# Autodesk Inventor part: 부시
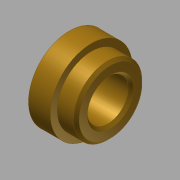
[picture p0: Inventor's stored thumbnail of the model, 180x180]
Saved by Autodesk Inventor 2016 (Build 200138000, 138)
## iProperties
Created: 2016-05
Part Number: 부시
Document SubType Name: Modeling
Designer: mduedu
Density: 7.86 g/cm^3
Material: 강철, 연강
Appearance: 황동 - 새틴
Author: mduedu
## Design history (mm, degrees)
sketch "스케치1"
  geometry: L1 (0, 0)-(15, 0); L2 (0, 7.5)-(15, 7.5); L3 (15, 7.5)-(15, 12.5); L4 (15, 12.5)-(8, 12.5); L5 (8, 12.5)-(8, 15); L6 (8, 15)-(0, 15); L7 (0, 15)-(0, 7.5)
  constraints: 14 end point, 4 parallel, 2 vertical alignment, 1 horizontal, 1 perpendicular, 1 vertical
  dimensions: "d0" = 15 distance of L1.start L1.end; "d1" = 15 diameter of L2 L1; "d2" = 25 diameter of L4 L1; "d3" = 8 distance of L5.end L6.end; "d4" = 30 diameter of L6 L1
revolve "회전1" sketch "스케치1" stored, may be unused: angle "d5" = 90 deg
chamfer "모따기1" distance "d6" = 1; stored, may be unused: second distance "d7" = 2, angle "d8" = 45 deg
chamfer "모따기2" distance "d9" = 1; stored, may be unused: second distance "d10" = 2, angle "d11" = 45 deg
node "솔리드1"
